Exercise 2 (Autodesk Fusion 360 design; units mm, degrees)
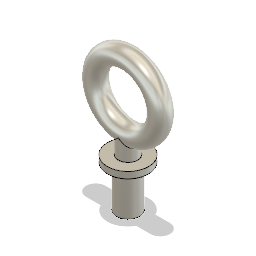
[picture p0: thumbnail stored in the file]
sketch "Sketch1" plane through (0, 0, 0) normal (0, 1, 0) x axis (1, 0, 0)
  line L1 (0, 0) -> (38.3397, 0)
  line L2 (0, 24.3662) -> (0, 0)
  circle C1 centre (25, 0) radius 7.5
  point P1 (0, 0)
  point P3 (0, 0)
  point P5 (25, 0)
  coincident P1 P3
  horizontal L1
  perpendicular L1 L2
  coincident L1 P5
  dimension "d1" diameter C1 = 15
  dimension "d3" = 50
revolve "Revolve1" sketch "Sketch1" AlongAngle 360
work_plane "WorkPlane1" AlongDistance -40
sketch "Sketch2" plane through (0, -40, 0) normal (0, 1, 0) x axis (1, 0, 0)
  circle C1 centre (0, 0) radius 7.5
  point P1 (0, 0)
  point P2 (0, 0)
  coincident P1 P2
  dimension "d6" diameter C1 = 15
extrude "Extrude1" add sketch "Sketch2" to an object
sketch "Sketch4" plane through (0, -40, 0) normal (0, -1, 0) x axis (1, 0, 0)
  circle C1 centre (0, 0) radius 7.5
  circle C2 centre (0, 0) radius 16
  concentric C1 C2
  dimension "d12" diameter C2 = 32
extrude "Extrude3" add sketch "Sketch4" along normal blind 5
sketch "Sketch5" plane through (0, -45, 0) normal (0, -1, 0) x axis (1, 0, 0)
  circle C1 centre (0, 0) radius 16
  circle C2 centre (0, 0) radius 9
  point P1 (0, 0)
  point P3 (0, 0)
  coincident P1 P3
  dimension "d15" diameter C2 = 18
extrude "Extrude4" add sketch "Sketch5" profile of C2 along normal blind 32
